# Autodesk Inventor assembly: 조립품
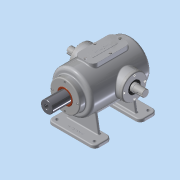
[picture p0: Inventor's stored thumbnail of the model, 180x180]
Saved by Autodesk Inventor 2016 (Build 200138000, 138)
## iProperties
Created: 2018-11
Part Number: 조립품
Material: 일반
Document SubType Name: Assembly
Designer: 공506_39
Mass: 8191.27 g
Surface Area: 4241.81 cm^2
Volume: 1855.49 cm^3
Density: 4.41462 g/cm^3
Author: 공506_39
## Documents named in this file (15)
- C:\Users\공506_39\Desktop\381121V1001\조립품.iam
- C:\Users\공506_39\Desktop\381121V1001\가변스프링.ipt
- C:\Users\공506_39\Desktop\381121V1001\베어링 6205.ipt
- 베어링 6205.ipt
- C:\Users\공506_39\Desktop\381121V1001\본체.ipt
- C:\Users\공506_39\Desktop\381121V1001\볼트 M4x0.7.ipt
- C:\Users\공506_39\Desktop\381121V1001\부시.ipt
- C:\Users\공506_39\Desktop\381121V1001\상부커버.ipt
- C:\Users\공506_39\Desktop\381121V1001\슬라이드 커버.ipt
- C:\Users\공506_39\Desktop\381121V1001\슬라이드.ipt
- C:\Users\공506_39\Desktop\381121V1001\오일실.ipt
- 오일실.ipt
- C:\Users\공506_39\Desktop\381121V1001\육각머리볼트 M4.ipt
- C:\Users\공506_39\Desktop\381121V1001\축 커버.ipt
- C:\Users\공506_39\Desktop\381121V1001\편심축.ipt
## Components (13 placed, 2 different names)
1. 가변스프링:1
2. M4x0.7:2
3. M4x0.7:4
4. M4x0.7:5
5. M4x0.7:6
6. M4x0.7:3
7. M4x0.7:7
8. M4x0.7:8
9. M4x0.7:9
10. M4x0.7:1
11. M4x0.7:10
12. M4x0.7:11
13. M4x0.7:12
